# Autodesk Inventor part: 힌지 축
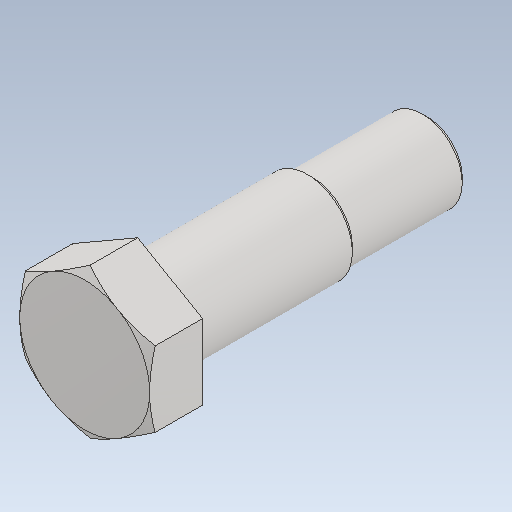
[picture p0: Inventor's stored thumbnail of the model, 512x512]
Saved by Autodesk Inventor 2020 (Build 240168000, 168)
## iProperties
Created: 2024-04
Part Number: 힌지 축
Material: 스테인리스강
Document SubType Name: Modeling
Designer: oem
Density: 8.08 g/cm^3
Appearance: 기본값
Mass: 19.8099 g
Surface Area: 13.175 cm^2
Volume: 2.45172 cm^3
Sending System: Autodesk Inventor 2025
Preprocessor: ST-DEVELOPER v20
Author: jhkim
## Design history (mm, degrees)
feature "솔리드1"
node "솔리드2"
